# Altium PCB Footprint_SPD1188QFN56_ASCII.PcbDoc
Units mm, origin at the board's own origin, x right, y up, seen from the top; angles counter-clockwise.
Board outline 152.4 x 101.6 mm, 2 copper layers (Top Layer, Bottom Layer); 1 components, 0 nets, 61 pads, 16 vias.
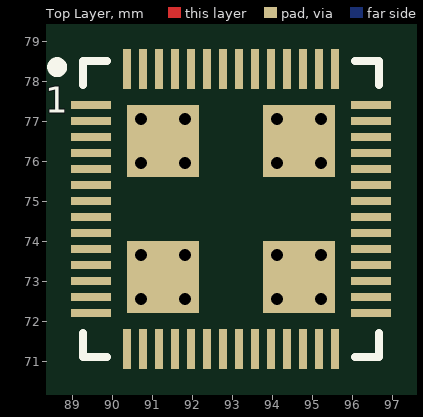
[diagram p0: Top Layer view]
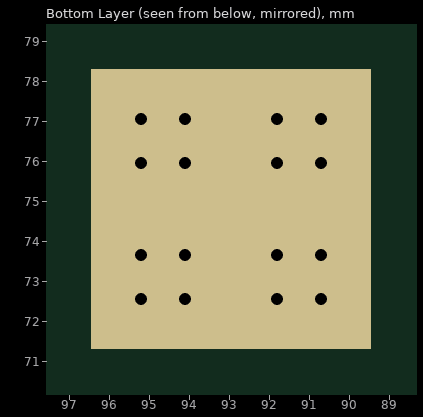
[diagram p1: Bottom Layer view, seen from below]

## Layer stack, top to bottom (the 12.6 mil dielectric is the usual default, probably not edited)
Top Solder: solder mask 0.0102, Solder Resist, Dk 3.5
Top Layer: signal copper 0.0356
Dielectric 1: dielectric 0.32, FR-4, Dk 4.8
Bottom Layer: signal copper 0.0356
Bottom Solder: solder mask 0.0102, Solder Resist, Dk 3.5

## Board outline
25.4,25.4 177.8,25.4 177.8,127 25.4,127

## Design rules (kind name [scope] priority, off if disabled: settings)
AssemblyTestPointUsage [All] p0: scope1count=1 scope1_0_kind=Board scope1_0_value=Board scope2count=1 scope2_0_kind=Board scope2_0_value=Board commentlength=0
AssemblyTestpoint [All] p0: scope1count=1 scope1_0_kind=Board scope1_0_value=Board scope2count=1 scope2_0_kind=Board scope2_0_value=Board commentlength=0
Clearance [All] p0: scope1count=1 scope1_0_kind=Board scope1_0_value=Board scope2count=1 scope2_0_kind=Board scope2_0_value=Board commentlength=0 gap=0.254
Clearance [All] p1: gap=0.254 ignorepadtopadclearanceinfootprint=FALSE except(0: Arc-Hole Track-Hole SMDPad-Hole THPad-Hole Via-Hole Fill-Hole Poly-Hole Region-Hole Text-Hole)
ComponentClearance [All] p0: scope1count=1 scope1_0_kind=Board scope1_0_value=Board scope2count=1 scope2_0_kind=Board scope2_0_value=Board commentlength=0 gap=0.254 collisioncheckmode=3
DiffPairsRouting [All] p0: scope1count=1 scope1_0_kind=Board scope1_0_value=Board scope2count=1 scope2_0_kind=Board scope2_0_value=Board commentlength=0
FabricationTestPointUsage [All] p0: scope1count=1 scope1_0_kind=Board scope1_0_value=Board scope2count=1 scope2_0_kind=Board scope2_0_value=Board commentlength=0 valid=0 allowmultiple=FALSE
FabricationTestpoint [All] p0: scope1count=1 scope1_0_kind=Board scope1_0_value=Board scope2count=1 scope2_0_kind=Board scope2_0_value=Board commentlength=0 side=3 testpointundercomponent=TRUE minsize=1.016 maxsize=2.54 preferedsize=1.524 minholesize=0 maxholesize=1.016 preferedholesize=0.813 testpointgrid=0.025
FanoutControl Fanout_BGA [All] p0 off: scope1count=1 scope1_0_kind=Board scope1_0_value=Board scope2count=1 scope2_0_kind=Board scope2_0_value=Board commentlength=69 // Protel DXP Scope 1 Expression Was: IsBGA   Fanout_BGA (Default Rule)
FanoutControl Fanout_LCC [All] p0 off: scope1count=1 scope1_0_kind=Board scope1_0_value=Board scope2count=1 scope2_0_kind=Board scope2_0_value=Board commentlength=69 // Protel DXP Scope 1 Expression Was: IsLCC   Fanout_LCC (Default Rule)
FanoutControl Fanout_SOIC [All] p0 off: scope1count=1 scope1_0_kind=Board scope1_0_value=Board scope2count=1 scope2_0_kind=Board scope2_0_value=Board commentlength=71 // Protel DXP Scope 1 Expression Was: IsSOIC   Fanout_SOIC (Default Rule)
FanoutControl Fanout_Small [All] p0 off: scope1count=1 scope1_0_kind=Board scope1_0_value=Board scope2count=1 scope2_0_kind=Board scope2_0_value=Board commentlength=84 // Protel DXP Scope 1 Expression Was: (CompPinCount < 5)   Fanout_Small (Default Rule)
FanoutControl Fanout_Default [All] p0: scope1count=1 scope1_0_kind=Board scope1_0_value=Board scope2count=1 scope2_0_kind=Board scope2_0_value=Board commentlength=30 // Fanout_Default (Default Rule)
Height [All] p0: scope1count=1 scope1_0_kind=Board scope1_0_value=Board scope2count=1 scope2_0_kind=Board scope2_0_value=Board commentlength=0
HoleSize [All] p0: scope1count=1 scope1_0_kind=Board scope1_0_value=Board scope2count=1 scope2_0_kind=Board scope2_0_value=Board commentlength=0 absolutevalues=TRUE maxlimit=2.54 minlimit=0.025 maxpercent=80.000 minpercent=20.000
HoleToHoleClearance [All] p0: scope1count=1 scope1_0_kind=Board scope1_0_value=Board scope2count=1 scope2_0_kind=Board scope2_0_value=Board commentlength=0
LayerPairs [All] p0: scope1count=1 scope1_0_kind=Board scope1_0_value=Board scope2count=1 scope2_0_kind=Board scope2_0_value=Board commentlength=0 enforce=TRUE
MinimumSolderMaskSliver [All] p0: scope1count=1 scope1_0_kind=Board scope1_0_value=Board scope2count=1 scope2_0_kind=Board scope2_0_value=Board commentlength=0
NetAntennae [All] p0: scope1count=1 scope1_0_kind=Board scope1_0_value=Board scope2count=1 scope2_0_kind=Board scope2_0_value=Board commentlength=0
PasteMaskExpansion [All] p0: scope1count=1 scope1_0_kind=Board scope1_0_value=Board scope2count=1 scope2_0_kind=Board scope2_0_value=Board commentlength=0 expansion=0
PlaneClearance [All] p0: scope1count=1 scope1_0_kind=Board scope1_0_value=Board scope2count=1 scope2_0_kind=Board scope2_0_value=Board commentlength=0 clearance=0.508
PlaneConnect [All] p0: scope1count=1 scope1_0_kind=Board scope1_0_value=Board scope2count=1 scope2_0_kind=Board scope2_0_value=Board commentlength=0 planeconnectstyle=Relief reliefexpansion=0.508 reliefentries=4 reliefconductorwidth=0.254 reliefairgap=0.254
PolygonConnect [All] p0: scope1count=1 scope1_0_kind=Board scope1_0_value=Board scope2count=1 scope2_0_kind=Board scope2_0_value=Board commentlength=0 connectstyle=Relief reliefconductorwidth=0.254 reliefentries=4 polygonreliefangle="90 Angle"
PolygonConnect [All] p1: connectstyle=Relief reliefconductorwidth=0.254 reliefentries=4 polygonreliefangle="90 Angle" airgapwidth=0.254
RoutingCorners [All] p0: scope1count=1 scope1_0_kind=Board scope1_0_value=Board scope2count=1 scope2_0_kind=Board scope2_0_value=Board commentlength=0 cornerstyle=45-Degree minsetback=2.54 maxsetback=2.54
RoutingLayers [All] p0: scope1count=1 scope1_0_kind=Board scope1_0_value=Board scope2count=1 scope2_0_kind=Board scope2_0_value=Board commentlength=0 top layer=Automatic bottom layer=Automatic
RoutingPriority [All] p0: scope1count=1 scope1_0_kind=Board scope1_0_value=Board scope2count=1 scope2_0_kind=Board scope2_0_value=Board commentlength=0
RoutingTopology [All] p0: scope1count=1 scope1_0_kind=Board scope1_0_value=Board scope2count=1 scope2_0_kind=Board scope2_0_value=Board commentlength=0 topology=Shortest
RoutingVias [All] p0: scope1count=1 scope1_0_kind=Board scope1_0_value=Board scope2count=1 scope2_0_kind=Board scope2_0_value=Board commentlength=0 holewidth=0.711 width=1.27 viastyle="Through Hole" minholewidth=0.711 minwidth=1.27 maxholewidth=0.711 maxwidth=1.27
RoutingVias [All] p1: holewidth=0.711 width=1.27 viastyle="Through Hole" minholewidth=0.711 minwidth=1.27 maxholewidth=0.711 maxwidth=1.27
ShortCircuit [All] p0: scope1count=1 scope1_0_kind=Board scope1_0_value=Board scope2count=1 scope2_0_kind=Board scope2_0_value=Board commentlength=0 allowed=FALSE
SilkToBoardRegionClearance [All] p0: scope1count=1 scope1_0_kind=Board scope1_0_value=Board scope2count=1 scope2_0_kind=Board scope2_0_value=Board commentlength=0
SilkToSilkClearance [All] p0: scope1count=1 scope1_0_kind=Board scope1_0_value=Board scope2count=1 scope2_0_kind=Board scope2_0_value=Board commentlength=0
SilkToSolderMaskClearance [All] p0 off: scope1count=1 scope1_0_kind=Board scope1_0_value=Board scope2count=1 scope2_0_kind=Board scope2_0_value=Board commentlength=44 // Protel DXP Scope 1 Expression Was: IsPad
SolderMaskExpansion [All] p0: scope1count=1 scope1_0_kind=Board scope1_0_value=Board scope2count=1 scope2_0_kind=Board scope2_0_value=Board commentlength=0 expansion=0.102
SolderMaskExpansion [All] p1: expansion=0.102 istentingtop=FALSE
UnRoutedNet [All] p0: scope1count=1 scope1_0_kind=Board scope1_0_value=Board scope2count=1 scope2_0_kind=Board scope2_0_value=Board commentlength=0
UnpouredPolygon [All] p0: scope1count=1 scope1_0_kind=Board scope1_0_value=Board scope2count=1 scope2_0_kind=Board scope2_0_value=Board commentlength=0
Width [All] p0: scope1count=1 scope1_0_kind=Board scope1_0_value=Board scope2count=1 scope2_0_kind=Board scope2_0_value=Board commentlength=0 maxlimit=0.254 minlimit=0.254 preferedwidth=0.254
Width [All] p1: maxlimit=0.254 minlimit=0.254 preferedwidth=0.254
30 further rules are at their usual default settings.

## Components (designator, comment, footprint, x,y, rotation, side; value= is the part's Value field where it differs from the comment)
? "" QFN-56-0.4 92.964,74.803 r0 top

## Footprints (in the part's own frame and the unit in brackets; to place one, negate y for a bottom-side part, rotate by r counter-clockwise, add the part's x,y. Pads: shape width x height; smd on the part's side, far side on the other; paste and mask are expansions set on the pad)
QFN-56-0.4 [mm] "P0.4,7*7mm"
  rect 1.8x1.8 smd: 0(-1.7,-1.7) 0(-1.7,1.7) 0(1.7,-1.7) 0(1.7,1.7)
  rect 7x7 smd far side: 0(0,0)
  rect 1x0.2 smd: 1(-3.5,2.6) 2(-3.5,2.2) 3(-3.5,1.8) 4(-3.5,1.4) 5(-3.5,1) 6(-3.5,0.6) 7(-3.5,0.2) 8(-3.5,-0.2) 9(-3.5,-0.6) 10(-3.5,-1) 11(-3.5,-1.4) 12(-3.5,-1.8) 13(-3.5,-2.2) 14(-3.5,-2.6) 29(3.5,-2.6) 30(3.5,-2.2) 31(3.5,-1.8) 32(3.5,-1.4) 33(3.5,-1) 34(3.5,-0.6) 35(3.5,-0.2) 36(3.5,0.2) 37(3.5,0.6) 38(3.5,1) 39(3.5,1.4) 40(3.5,1.8) 41(3.5,2.2) 42(3.5,2.6)
  rect 0.2x1 smd: 15(-2.6,-3.5) 16(-2.2,-3.5) 17(-1.8,-3.5) 18(-1.4,-3.5) 19(-1,-3.5) 20(-0.6,-3.5) 21(-0.2,-3.5) 22(0.2,-3.5) 23(0.6,-3.5) 24(1,-3.5) 25(1.4,-3.5) 26(1.8,-3.5) 27(2.2,-3.5) 28(2.6,-3.5) 43(2.6,3.5) 44(2.2,3.5) 45(1.8,3.5) 46(1.4,3.5) 47(1,3.5) 48(0.6,3.5) 49(0.2,3.5) 50(-0.2,3.5) 51(-0.6,3.5) 52(-1,3.5) 53(-1.4,3.5) 54(-1.8,3.5) 55(-2.2,3.5) 56(-2.6,3.5)
  silkscreen extent -4.47,-3.7 3.7,3.7

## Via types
v1: diameter 0.6, hole 0.3, Top Layer to Bottom Layer, 16 vias

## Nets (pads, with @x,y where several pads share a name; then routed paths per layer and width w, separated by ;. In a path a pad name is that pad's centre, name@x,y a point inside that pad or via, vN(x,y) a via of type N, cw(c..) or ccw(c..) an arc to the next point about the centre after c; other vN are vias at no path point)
pads on no net: ?.0 ?.1 ?.2 ?.3 ?.4 ?.5 ?.6 ?.7 ?.8 ?.9 ?.10 ?.11 ?.12 ?.13 ?.14 ?.15 ?.16 ?.17 ?.18 ?.19 ?.20 ?.21 ?.22 ?.23 ?.24 ?.25 ?.26 ?.27 ?.28 ?.29 ?.30 ?.31 ?.32 ?.33 ?.34 ?.35 ?.36 ?.37 ?.38 ?.39 ?.40 ?.41 ?.42 ?.43 ?.44 ?.45 ?.46 ?.47 ?.48 ?.49 ?.50 ?.51 ?.52 ?.53 ?.54 ?.55 ?.56
copper on no net:
  other v1: 90.714,72.553 91.814,72.553 94.114,72.553 95.214,72.553 90.714,73.653 91.814,73.653 94.114,73.653 95.214,73.653 90.714,75.953 91.814,75.953 94.114,75.953 95.214,75.953 90.714,77.053 91.814,77.053 94.114,77.053 95.214,77.053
